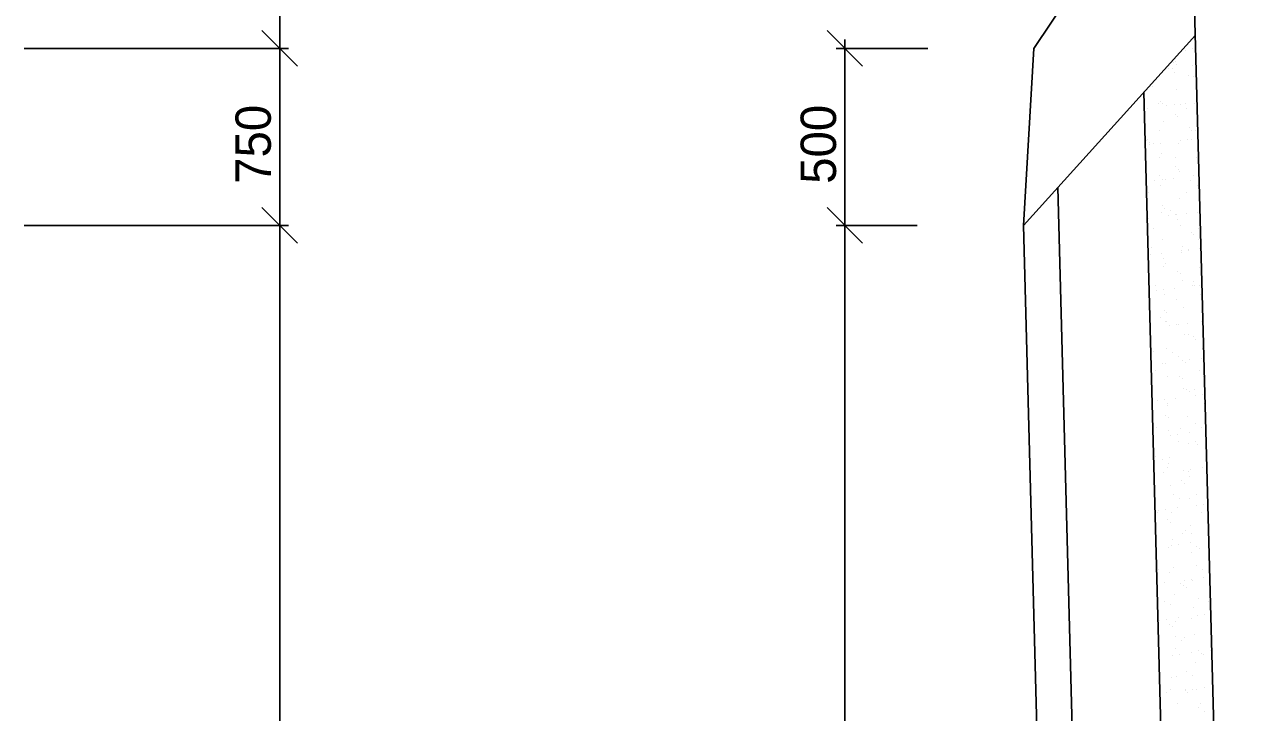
# Model space of a CAD drawing. Extents: x -2363 to 18637, y 14070 to 28920.
# Drawn here: x 10090 to 13525, y 23963 to 25908 of the extents above; entities that cross this region are included whole.
import ezdxf

# ---------------------------------------------------------------- set-up
doc = ezdxf.new("R2010")
doc.units = 0
for name, color, linetype in [('KÓTY', 7, 'Continuous'), ('OBRYS', 7, 'Continuous'), ('SJEZD', 7, 'Continuous'), ('ŠRAFY', 7, 'Continuous')]:
    doc.layers.add(name, color=color, linetype=linetype)

# ---------------------------------------------------------------- blocks, each defined once
blk = doc.blocks.new('_ARCHTICK')
blk.add_lwpolyline([(-0.5, -0.5), (0.5, 0.5)])

msp = doc.modelspace()

# ---------------------------------------------------------------- linework, layer by layer
at = {"layer": 'KÓTY'}
for p, q in [((10811.4, 25814.7), (10811.4, 26864.7)), ((10761.4, 25889.7), (10861.4, 25789.7)), ((10861.4, 25789.7), (10761.4, 25889.7)), ((10090.2, 25839.7), (10836.4, 25839.7)), ((10090.2, 25839.7), (10836.4, 25839.7)), ((10811.4, 25314.7), (10811.4, 25864.7)), ((12641.6, 25839.7), (12382.6, 25839.7)), ((12407.6, 25314.7), (12407.6, 25864.7)), ((10761.4, 25389.7), (10861.4, 25289.7)), ((10861.4, 25289.7), (10761.4, 25389.7)), ((10811.4, 22314.7), (10811.4, 25364.7)), ((12407.6, 22314.7), (12407.6, 25364.7)), ((10090.2, 25339.7), (10836.4, 25339.7)), ((10090.2, 25339.7), (10836.4, 25339.7)), ((12611.6, 25339.7), (12382.6, 25339.7)), ((12611.6, 25339.7), (12382.6, 25339.7))]:
    msp.add_line(p, q, dxfattribs=at)
at = {"layer": 'OBRYS'}
for p, q in [((12941.6, 25839.7), (13220.6, 26258.2)), ((13525.3, 21092.9), (13387.1, 26258.2)), ((12911.6, 25339.7), (12941.6, 25839.7)), ((12991.9, 22339.7), (12911.6, 25339.7))]:
    msp.add_line(p, q, dxfattribs=at)
at = {"layer": 'SJEZD'}
for p, q in [((12941.6, 25839.7), (13220.6, 26258.2)), ((13387.1, 26258.2), (13525.3, 21092.9)), ((12911.6, 25339.7), (13397.3, 25876.6)), ((12941.6, 25839.7), (12911.6, 25339.7)), ((13251.6, 25715.5), (13369.1, 21324.7)), ((13008.7, 25447), (13094.3, 22247.1)), ((12911.6, 25339.7), (12991.9, 22339.7))]:
    msp.add_line(p, q, dxfattribs=at)
at = {"layer": 'ŠRAFY'}
for p, q in [((13368.1, 25832.3), (13368.1, 25832.3)), ((13389.5, 25838.4), (13389.5, 25838.4)), ((13336.3, 25800.8), (13336.3, 25800.8)), ((13341.3, 25801.4), (13341.3, 25801.4)), ((13322.8, 25781.6), (13322.8, 25781.6)), ((13333.6, 25782.7), (13333.6, 25782.7)), ((13339.7, 25770.8), (13339.7, 25770.8)), ((13343.6, 25794), (13343.6, 25794)), ((13387.9, 25789.9), (13387.9, 25789.9)), ((13275.8, 25731.9), (13275.8, 25731.9)), ((13378.4, 25762.2), (13378.4, 25762.2)), ((13392, 25761.3), (13392, 25761.3)), ((13400.4, 25732.1), (13400.4, 25732.1)), ((13343.8, 25724.3), (13343.8, 25724.3)), ((13262.8, 25669.8), (13262.8, 25669.8)), ((13292.2, 25684.7), (13292.2, 25684.7)), ((13298, 25690.6), (13298, 25690.6)), ((13305.4, 25683.8), (13305.4, 25683.8)), ((13317.1, 25677), (13317.1, 25677)), ((13338, 25679.7), (13338, 25679.7)), ((13355.1, 25681.4), (13355.1, 25681.4)), ((13370.5, 25684), (13370.5, 25684)), ((13372, 25670.6), (13372, 25670.6)), ((13394.6, 25684.3), (13394.6, 25684.3)), ((13308.1, 25631.7), (13308.1, 25631.7)), ((13340.2, 25651.9), (13340.2, 25651.9)), ((13346.3, 25647.2), (13346.3, 25647.2)), ((13294.8, 25607.7), (13294.8, 25607.7)), ((13380, 25615.4), (13380, 25615.4)), ((13387.4, 25608.7), (13387.4, 25608.7)), ((13397.1, 25607.2), (13397.1, 25607.2)), ((13259.7, 25580.3), (13259.7, 25580.3)), ((13262.9, 25581), (13262.9, 25581)), ((13267.1, 25573.6), (13267.1, 25573.6)), ((13267.2, 25566.8), (13267.2, 25566.8)), ((13279.7, 25570.3), (13279.7, 25570.3)), ((13299.7, 25571.1), (13299.7, 25571.1)), ((13348.8, 25570.2), (13348.8, 25570.2)), ((13354, 25578.3), (13354, 25578.3)), ((13374.8, 25581), (13374.8, 25581)), ((13387.4, 25581.2), (13387.4, 25581.2)), ((13404.3, 25570.5), (13404.3, 25570.5)), ((13297.3, 25530.6), (13297.3, 25530.6)), ((13301.9, 25541.7), (13301.9, 25541.7)), ((13340.4, 25531.6), (13340.4, 25531.6)), ((13399.6, 25530.1), (13399.6, 25530.1)), ((13341.7, 25505.2), (13341.7, 25505.2)), ((13349.1, 25498.5), (13349.1, 25498.5)), ((13351.4, 25493.1), (13351.4, 25493.1)), ((13283.2, 25465.4), (13283.2, 25465.4)), ((13295.2, 25480.8), (13295.2, 25480.8)), ((13304, 25468.1), (13304, 25468.1)), ((13312, 25470.1), (13312, 25470.1)), ((13336.6, 25472.4), (13336.6, 25472.4)), ((13383.9, 25466.6), (13383.9, 25466.6)), ((13390.9, 25479.6), (13390.9, 25479.6)), ((13263.7, 25431.5), (13263.7, 25431.5)), ((13299.8, 25453.5), (13299.8, 25453.5)), ((13372.7, 25431.4), (13372.7, 25431.4)), ((13402.1, 25453), (13402.1, 25453)), ((13303.5, 25395), (13303.5, 25395)), ((13310.8, 25388.2), (13310.8, 25388.2)), ((13353.9, 25416), (13353.9, 25416)), ((13265.8, 25359.5), (13265.8, 25359.5)), ((13302.3, 25376.5), (13302.3, 25376.5)), ((13320.1, 25366.7), (13320.1, 25366.7)), ((13327.5, 25380.7), (13327.5, 25380.7)), ((13340.9, 25369.4), (13340.9, 25369.4)), ((13344.3, 25369.9), (13344.3, 25369.9)), ((13345.6, 25356.3), (13345.6, 25356.3)), ((13373.4, 25373.7), (13373.4, 25373.7)), ((13404.6, 25376), (13404.6, 25376)), ((13280.5, 25331), (13280.5, 25331)), ((13356.4, 25339), (13356.4, 25339)), ((13385.5, 25319.9), (13385.5, 25319.9)), ((13405.1, 25331.2), (13405.1, 25331.2)), ((13265.2, 25284.7), (13265.2, 25284.7)), ((13304.8, 25299.4), (13304.8, 25299.4)), ((13392.8, 25313.1), (13392.8, 25313.1)), ((13407.2, 25298.9), (13407.2, 25298.9)), ((13270.1, 25256.5), (13270.1, 25256.5)), ((13272.6, 25278), (13272.6, 25278)), ((13302.6, 25260.8), (13302.6, 25260.8)), ((13357, 25268), (13357, 25268)), ((13358.9, 25261.9), (13358.9, 25261.9)), ((13359.8, 25280.5), (13359.8, 25280.5)), ((13376.6, 25269.8), (13376.6, 25269.8)), ((13377.8, 25270.7), (13377.8, 25270.7)), ((13410.3, 25275), (13410.3, 25275)), ((13307.4, 25246.1), (13307.4, 25246.1)), ((13307.4, 25222.3), (13307.4, 25222.3)), ((13312.8, 25230.9), (13312.8, 25230.9)), ((13409.7, 25221.8), (13409.7, 25221.8)), ((13267.5, 25180.1), (13267.5, 25180.1)), ((13347.2, 25209.6), (13347.2, 25209.6)), ((13354.6, 25202.9), (13354.6, 25202.9)), ((13361.4, 25184.8), (13361.4, 25184.8)), ((13392.1, 25180.3), (13392.1, 25180.3)), ((13284.4, 25169.4), (13284.4, 25169.4)), ((13286.2, 25155.1), (13286.2, 25155.1)), ((13307, 25157.8), (13307, 25157.8)), ((13309.9, 25145.2), (13309.9, 25145.2)), ((13339.5, 25162.1), (13339.5, 25162.1)), ((13389.4, 25171), (13389.4, 25171)), ((13393.9, 25169.3), (13393.9, 25169.3)), ((13408.9, 25169.6), (13408.9, 25169.6)), ((13414.7, 25172), (13414.7, 25172)), ((13269.1, 25135.9), (13269.1, 25135.9)), ((13345.1, 25130.7), (13345.1, 25130.7)), ((13412.2, 25144.7), (13412.2, 25144.7)), ((13299.8, 25080), (13299.8, 25080)), ((13308.9, 25099.4), (13308.9, 25099.4)), ((13316.3, 25092.6), (13316.3, 25092.6)), ((13364, 25107.7), (13364, 25107.7)), ((13312.4, 25068.2), (13312.4, 25068.2)), ((13316.7, 25069.2), (13316.7, 25069.2)), ((13323.1, 25056.4), (13323.1, 25056.4)), ((13343.9, 25059.1), (13343.9, 25059.1)), ((13351.1, 25060.7), (13351.1, 25060.7)), ((13376.4, 25063.4), (13376.4, 25063.4)), ((13414.7, 25067.7), (13414.7, 25067.7)), ((13366.5, 25030.7), (13366.5, 25030.7)), ((13377.4, 25030.5), (13377.4, 25030.5)), ((13390.9, 25024.3), (13390.9, 25024.3)), ((13398.3, 25017.5), (13398.3, 25017.5)), ((13278.1, 24982.4), (13278.1, 24982.4)), ((13314.9, 24991.1), (13314.9, 24991.1)), ((13332.1, 24979.8), (13332.1, 24979.8)), ((13417.2, 24990.6), (13417.2, 24990.6)), ((13273.1, 24946.2), (13273.1, 24946.2)), ((13305.6, 24950.5), (13305.6, 24950.5)), ((13312.9, 24950.5), (13312.9, 24950.5)), ((13349, 24969), (13349, 24969)), ((13359.9, 24957.7), (13359.9, 24957.7)), ((13369, 24953.6), (13369, 24953.6)), ((13380.8, 24960.4), (13380.8, 24960.4)), ((13413.3, 24964.7), (13413.3, 24964.7)), ((13285.1, 24930.1), (13285.1, 24930.1)), ((13317.4, 24914), (13317.4, 24914)), ((13352.7, 24914), (13352.7, 24914)), ((13360, 24907.3), (13360, 24907.3)), ((13409.7, 24930.4), (13409.7, 24930.4)), ((13419.8, 24913.5), (13419.8, 24913.5)), ((13364.4, 24879.6), (13364.4, 24879.6)), ((13371.5, 24876.5), (13371.5, 24876.5)), ((13394.8, 24875.4), (13394.8, 24875.4)), ((13289.2, 24844.8), (13289.2, 24844.8)), ((13310, 24847.5), (13310, 24847.5)), ((13320, 24836.9), (13320, 24836.9)), ((13342.5, 24851.8), (13342.5, 24851.8)), ((13381.3, 24868.9), (13381.3, 24868.9)), ((13396.8, 24858.9), (13396.8, 24858.9)), ((13417.6, 24861.7), (13417.6, 24861.7)), ((13422.3, 24836.5), (13422.3, 24836.5)), ((13314.4, 24803.8), (13314.4, 24803.8)), ((13317.4, 24830), (13317.4, 24830)), ((13289, 24768.5), (13289, 24768.5)), ((13321.8, 24797), (13321.8, 24797)), ((13374, 24799.4), (13374, 24799.4)), ((13396.7, 24779.5), (13396.7, 24779.5)), ((13413.6, 24768.7), (13413.6, 24768.7)), ((13322.5, 24759.9), (13322.5, 24759.9)), ((13326, 24746.1), (13326, 24746.1)), ((13346.9, 24748.8), (13346.9, 24748.8)), ((13356.6, 24765.2), (13356.6, 24765.2)), ((13379.4, 24753.1), (13379.4, 24753.1)), ((13424.8, 24759.4), (13424.8, 24759.4)), ((13349.8, 24729.8), (13349.8, 24729.8)), ((13376.6, 24722.4), (13376.6, 24722.4)), ((13396.4, 24728.7), (13396.4, 24728.7)), ((13403.8, 24721.9), (13403.8, 24721.9)), ((13283.5, 24686.8), (13283.5, 24686.8)), ((13304.5, 24679.1), (13304.5, 24679.1)), ((13321.3, 24668.3), (13321.3, 24668.3)), ((13325, 24682.8), (13325, 24682.8)), ((13427.3, 24682.3), (13427.3, 24682.3)), ((13429, 24679.3), (13429, 24679.3)), ((13308.6, 24640.2), (13308.6, 24640.2)), ((13318.3, 24654.9), (13318.3, 24654.9)), ((13362.9, 24647.4), (13362.9, 24647.4)), ((13379.1, 24645.3), (13379.1, 24645.3)), ((13383.7, 24650.1), (13383.7, 24650.1)), ((13416.3, 24654.4), (13416.3, 24654.4)), ((13327.5, 24605.7), (13327.5, 24605.7)), ((13358.1, 24618.4), (13358.1, 24618.4)), ((13365.5, 24611.7), (13365.5, 24611.7)), ((13382.1, 24629.6), (13382.1, 24629.6)), ((13429.8, 24605.2), (13429.8, 24605.2)), ((13336.8, 24578.9), (13336.8, 24578.9)), ((13353.6, 24568.2), (13353.6, 24568.2)), ((13381.6, 24568.2), (13381.6, 24568.2)), ((13400.3, 24579.8), (13400.3, 24579.8)), ((13289.8, 24529.3), (13289.8, 24529.3)), ((13292.1, 24534.5), (13292.1, 24534.5)), ((13312.9, 24537.2), (13312.9, 24537.2)), ((13330, 24528.7), (13330, 24528.7)), ((13345.5, 24541.5), (13345.5, 24541.5)), ((13399.8, 24548.6), (13399.8, 24548.6)), ((13414.4, 24529.5), (13414.4, 24529.5)), ((13420.6, 24551.4), (13420.6, 24551.4)), ((13432.4, 24528.2), (13432.4, 24528.2)), ((13319.9, 24508.2), (13319.9, 24508.2)), ((13327.2, 24501.5), (13327.2, 24501.5)), ((13362, 24469.6), (13362, 24469.6)), ((13369.1, 24478.7), (13369.1, 24478.7)), ((13384.1, 24491.1), (13384.1, 24491.1)), ((13385.9, 24468), (13385.9, 24468)), ((13322.1, 24429.1), (13322.1, 24429.1)), ((13329, 24435.8), (13329, 24435.8)), ((13332.5, 24451.6), (13332.5, 24451.6)), ((13349.8, 24438.5), (13349.8, 24438.5)), ((13382.3, 24442.8), (13382.3, 24442.8)), ((13401.9, 24433.1), (13401.9, 24433.1)), ((13409.2, 24426.3), (13409.2, 24426.3)), ((13434.9, 24451.1), (13434.9, 24451.1)), ((13289, 24391.2), (13289, 24391.2)), ((13386.6, 24414.1), (13386.6, 24414.1)), ((13293.7, 24367.6), (13293.7, 24367.6)), ((13323.8, 24359.3), (13323.8, 24359.3)), ((13335.1, 24374.5), (13335.1, 24374.5)), ((13401.4, 24378.6), (13401.4, 24378.6)), ((13418.3, 24367.8), (13418.3, 24367.8)), ((13437.4, 24374), (13437.4, 24374)), ((13311.6, 24329.9), (13311.6, 24329.9)), ((13354.4, 24328.9), (13354.4, 24328.9)), ((13363.6, 24322.8), (13363.6, 24322.8)), ((13365.9, 24337), (13365.9, 24337)), ((13386.7, 24339.8), (13386.7, 24339.8)), ((13389.2, 24337), (13389.2, 24337)), ((13419.2, 24344.1), (13419.2, 24344.1)), ((13337.6, 24297.4), (13337.6, 24297.4)), ((13371, 24316.1), (13371, 24316.1)), ((13309.1, 24278.2), (13309.1, 24278.2)), ((13326, 24267.4), (13326, 24267.4)), ((13391.7, 24259.9), (13391.7, 24259.9)), ((13405.8, 24284.2), (13405.8, 24284.2)), ((13433.7, 24278.4), (13433.7, 24278.4)), ((13295.1, 24224.2), (13295.1, 24224.2)), ((13315.9, 24226.9), (13315.9, 24226.9)), ((13340.1, 24220.4), (13340.1, 24220.4)), ((13348.4, 24231.2), (13348.4, 24231.2)), ((13386.7, 24228.8), (13386.7, 24228.8)), ((13402.8, 24238.3), (13402.8, 24238.3)), ((13423.6, 24241.1), (13423.6, 24241.1)), ((13325.3, 24212.6), (13325.3, 24212.6)), ((13332.7, 24205.9), (13332.7, 24205.9)), ((13341.4, 24178), (13341.4, 24178)), ((13358.3, 24167.3), (13358.3, 24167.3)), ((13367.5, 24174), (13367.5, 24174)), ((13394.2, 24182.9), (13394.2, 24182.9)), ((13294.5, 24128.4), (13294.5, 24128.4)), ((13332, 24125.4), (13332, 24125.4)), ((13342.6, 24143.3), (13342.6, 24143.3)), ((13352.8, 24128.2), (13352.8, 24128.2)), ((13385.3, 24132.5), (13385.3, 24132.5)), ((13407.3, 24137.5), (13407.3, 24137.5)), ((13414.7, 24130.7), (13414.7, 24130.7)), ((13419, 24128.6), (13419, 24128.6)), ((13439.6, 24139.6), (13439.6, 24139.6)), ((13396.7, 24105.8), (13396.7, 24105.8)), ((13329.2, 24063.7), (13329.2, 24063.7)), ((13345.1, 24066.2), (13345.1, 24066.2)), ((13373.7, 24077.9), (13373.7, 24077.9)), ((13390.6, 24067.1), (13390.6, 24067.1)), ((13314.5, 24019.6), (13314.5, 24019.6)), ((13326.8, 24028.2), (13326.8, 24028.2)), ((13368.9, 24026.7), (13368.9, 24026.7)), ((13369.1, 24027.3), (13369.1, 24027.3)), ((13376.4, 24020.5), (13376.4, 24020.5)), ((13389.7, 24029.5), (13389.7, 24029.5)), ((13399.2, 24028.7), (13399.2, 24028.7)), ((13422.2, 24033.8), (13422.2, 24033.8)), ((13347.7, 23989.1), (13347.7, 23989.1)), ((13406, 23977.7), (13406, 23977.7)), ((13411.2, 23988.6), (13411.2, 23988.6)), ((13422.9, 23967), (13422.9, 23967))]:
    msp.add_line(p, q, dxfattribs=at)

# ---------------------------------------------------------------- block references
at = {"layer": 'KÓTY', "xscale": 100, "yscale": 100}
for p, rotation in [((10811.4, 25839.7), 90), ((10811.4, 25839.7), -90.00000000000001), ((12407.6, 25839.7), 90), ((10811.4, 25339.7), 90), ((10811.4, 25339.7), -90.00000000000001), ((12407.6, 25339.7), 90), ((12407.6, 25339.7), -90.00000000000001)]:
    msp.add_blockref('_ARCHTICK', p, dxfattribs=dict(at, rotation=rotation))

# ---------------------------------------------------------------- texts
at = {"layer": 'KÓTY'}
for s, p in [('750', (10786.4, 25457.1)), ('500', (12382.6, 25457.1))]:
    msp.add_text(s, height=100, rotation=90, dxfattribs=at).set_placement(p)

doc.saveas('drawing.dxf')
